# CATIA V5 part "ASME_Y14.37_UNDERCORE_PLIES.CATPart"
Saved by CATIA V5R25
Part number: ASME_Y14.37_UNDERCORE_PLIES-301
Bounding box of the stored display mesh (mm): x -1012.309 to 1278.04, y -788.718 to 818.501, z 0 to 12.192
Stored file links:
  \\NW\Data\MSE-Composites\STEP Interoperability\ExampleData\ASME_Y14.37 Test Parts\ASSEMBLY VERSION\ASME_Y14.37_UNDERCORE_PLIES.CATPart
  C:\Users\jvl2147\Desktop\CompositesCatalog.CATMaterial
  \\Nw\787lib\787-PROCINT-WKG\Dom_SSDBS\DM\!!ShareFileForWritingServices\Composites\Standards and References\ASMEY-14.37\ASMEY-14.37_COMPOSITES.CATMaterial
  C:\Program Files\Dassault Systemes\B25SP2PRALL\win_b64\startup\materials\honeycomb.jpg
  \\Nw\787lib\787-PROCINT-WKG\Dom_SSDBS\DM\!!ShareFileForWritingServices\Composites\Standards and References\ASME Y14.37\PLY TABEL_-1 BOND ASSEMBLY.xlsx
  \\Nw\787lib\787-PROCINT-WKG\Dom_SSDBS\DM\!!ShareFileForWritingServices\Composites\Standards and References\ASME Y14.37\ASME_Y14.37_VALIDATION-PROPERTIES_CORE STIFFENED BOND PART.xlsx.xlsx
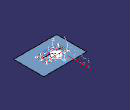
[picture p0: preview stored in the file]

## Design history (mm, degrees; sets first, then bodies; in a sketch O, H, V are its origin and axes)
Parameters
  StandardPlyThickness = 0.254 mm
  `Scale Value` = 100
CompParametersFeature1 "CATCoParametersFeatName": Value 0, Value 45, Value -45, Value 90, Orientations 999.999, Orientations 90
CompStacking1 "Stacking"
CompReviewTools1 "Review tools"
f4a2d38f3ddc11d3a929006094b99c4b_11 "CATTPSSet"
TTRSSet1
Set1 "CONSTRUCTION (REF)"
  Sketch1 on XY plane of AxisSystem2, origin (0, 0, 0), H (1, 0, 0), V (0, 1, 0)
    line L1 (-1012.309, 818.5005) -> (1278.0398, 818.5005)
    line L2 (1278.0398, 818.5005) -> (1278.0398, -788.7181)
    line L3 (1278.0398, -788.7181) -> (-1012.309, -788.7181)
    line L4 (-1012.309, -788.7181) -> (-1012.309, 818.5005)
    horizontal: L1 H, L3 H
    vertical: L2 V, L4 V
  Fill1: Boundary Sketch1
  CurvePar1: Offset CompStdContourFeature1, Support Fill1, Offset2 0, Offset1 50.8
  Plane1: type Offset, RefPlane YZ plane of AxisSystem2, Offset -598
  Plane2: type Offset, RefPlane YZ plane of AxisSystem2, Offset -598, reversed
  Plane3: type Offset, RefPlane ZX plane of AxisSystem2, Offset -292
  Plane4: type Offset, RefPlane ZX plane of AxisSystem2, Offset -292, reversed
  MultiSel1
  CompStdContourFeature1 "CATCoStdContourFeatName": SupportSurface Fill1, ClosedSetOfCurves ({intersect ToIntersect1 Plane2, ToIntersect2 Fill1}; {intersect ToIntersect1 Plane3, ToIntersect2 Fill1}; {intersect ToIntersect1 Plane1, ToIntersect2 Fill1}; {intersect ToIntersect1 Plane4, ToIntersect2 Fill1}), ExtrapolDist 0.2
  Plane5: type Offset, RefPlane Plane2, Offset 254, reversed
  Intersect1: ToIntersect1 Plane5, ToIntersect2 Fill1
  Plane6: type Offset, RefPlane Plane1, Offset 254
  Intersect2: ToIntersect1 Plane6, ToIntersect2 Fill1
  Plane7: type Offset, RefPlane ZX plane of AxisSystem2, Offset -50.8
  CurvePar2: Offset CompStdContourFeature1, Offset2 0, Offset1 139.7
  Point1: (0, 0, 0), in AxisSystem2
  AxisSystem1: origin (0, 0, -127), X (1, 0, 0), Y (0, 1, 0), Z (0, 0, 1)
  Point2: (215.6851, 77.4411, 0)
  Point3: type OnCurve, Support edge [ZX plane of AxisSystem2 | YZ plane of AxisSystem2], Length 127
  Point4: type OnPlane, Support Join1, H -130.714, V 273.957, Direction (1, 0, 0)
  Split1: ToCut Circle1, Cutting {intersect ToIntersect1 Plane4, ToIntersect2 Fill1}
  Circle1: type CtrRad, Start 0, End 180, Center Point4, Support Join1, Radius 76.2, FirstDirection (1, 0, 0)
Set2 "ENGINEERING GEOMETRY"
  Join1 "TOOLSIDE SURFACE": Elements Fill1
  AxisSystem2 "PLY ORIENTATION COORDINATE SYSTEM": origin (0, 0, 0), X (1, 0, 0), Y (0, 1, 0), Z (0, 0, 1)
Body1 "ASME_Y14.37_UNDERCORE_SOLID (REF)" (main body)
